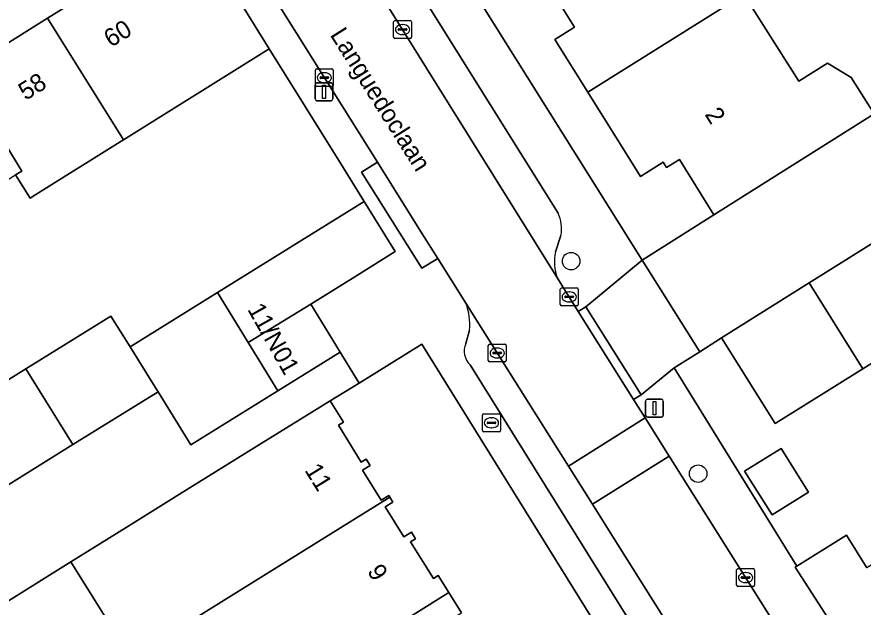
# Model space of a CAD drawing. Extents: x 157767 to 159172, y 387839 to 389425.
# Drawn here: x 158537.73 to 158585.08, y 388070.65 to 388103.69 of the extents above; entities that cross this region are included whole.
import ezdxf

# ---------------------------------------------------------------- set-up
doc = ezdxf.new("R2010")
doc.units = 0
for name, color, linetype in [('IMGEO_Boom', 7, 'Continuous'), ('IMGEO_Brandkraan', 7, 'Continuous'), ('IMGEO_Erf', 7, 'Continuous'), ('IMGEO_Kolk', 7, 'Continuous'), ('IMGEO_Lichtmast', 7, 'Continuous'), ('IMGEO_Muur', 7, 'Continuous'), ('IMGEO_Openbare_ruimte_label', 7, 'Continuous'), ('IMGEO_Pand', 7, 'Continuous'), ('IMGEO_Pand_nummerreeks', 7, 'Continuous'), ('IMGEO_Parkeervlak_open', 7, 'Continuous'), ('IMGEO_Rijbaan_lokaal_open', 7, 'Continuous'), ('IMGEO_Voetpad_open', 7, 'Continuous')]:
    doc.layers.add(name, color=color, linetype=linetype)

msp = doc.modelspace()

# ---------------------------------------------------------------- linework, layer by layer
at = {"layer": 'IMGEO_Boom'}
for centre in [(158568.743, 388090.013), (158575.85, 388078.115)]:
    msp.add_circle(centre, 0.489, dxfattribs=at)
at = {"layer": 'IMGEO_Brandkraan'}
for p, q in [((158563.785, 388080.537), (158563.785, 388081.389)), ((158563.86, 388081.463), (158564.712, 388081.463)), ((158564.273, 388081.243), (158564.298, 388081.243)), ((158564.786, 388081.389), (158564.786, 388080.537)), ((158564.044, 388080.957), (158564.044, 388080.969)), ((158564.482, 388080.92), (158564.084, 388080.92)), ((158564.087, 388081.006), (158564.485, 388081.006)), ((158564.296, 388080.683), (158564.271, 388080.683)), ((158564.528, 388080.969), (158564.528, 388080.957)), ((158564.712, 388080.463), (158563.86, 388080.463))]:
    msp.add_line(p, q, dxfattribs=at)
for points in [[(158563.785, 388080.537), (158563.785, 388081.389)], [(158563.86, 388081.463), (158564.712, 388081.463)], [(158564.786, 388081.389), (158564.786, 388080.537)], [(158564.712, 388080.463), (158563.86, 388080.463)]]:
    msp.add_lwpolyline(points, dxfattribs=at)
for centre, radius, start, end in [((158563.862, 388081.387), 0.0765, 91.552, 178.448), ((158563.862, 388081.387), 0.0765, 91.552, 178.448), ((158564.71, 388081.387), 0.0765, 1.552, 88.448), ((158564.71, 388081.387), 0.0765, 1.552, 88.448), ((158564.084, 388080.966), 0.0403, 85.8775, 175.7526), ((158564.081, 388080.956), 0.0366, 178.938, 274.7102), ((158564.485, 388080.963), 0.043, 264.8664, 352.4533), ((158564.489, 388080.968), 0.0386, 1.7309, 96.639), ((158563.862, 388080.539), 0.0765, 181.552, 268.448), ((158563.862, 388080.539), 0.0765, 181.552, 268.448), ((158564.71, 388080.539), 0.0765, 271.552, 358.448), ((158564.71, 388080.539), 0.0765, 271.552, 358.448)]:
    msp.add_arc(centre, radius, start, end, dxfattribs=at)
for centre, major_axis, ratio, start_param, end_param in [((158564.272, 388080.963), (-0.387, 0.002), 0.722429, 4.712389, 7.853982), ((158564.297, 388080.963), (-0.39, 0.002), 0.717154, 1.570796, 4.712389)]:
    msp.add_ellipse(centre, major_axis=major_axis, ratio=ratio, start_param=start_param, end_param=end_param, dxfattribs=at)
at = {"layer": 'IMGEO_Erf'}
for points in [[(158559.15, 388140.002), (158562.16, 388135.2), (158560.23, 388133.99), (158563.255, 388129.158), (158565.829, 388130.764), (158568.828, 388125.956), (158571.824, 388121.153), (158574.89, 388116.238), (158574.652, 388116.087), (158577.666, 388111.254), (158580.054, 388112.773), (158583.085, 388107.915), (158580.691, 388106.405), (158578.413, 388104.968), (158581.484, 388100.084), (158583.099, 388101.1), (158584.422, 388100.295), (158585.707, 388098.251)], [(158543.307, 388136.995), (158572.727, 388090.067), (158576.734, 388092.607), (158574.802, 388095.703), (158574.08, 388095.253), (158573.894, 388095.549), (158572.625, 388094.751), (158569.685, 388099.464), (158567.84, 388102.421), (158568.941, 388103.113), (158567.783, 388104.969)], [(158541.987, 388115.359), (158534.664, 388110.788), (158510.476, 388095.689), (158512.627, 388092.242), (158517.684, 388095.387), (158522.533, 388098.402), (158527.384, 388101.418), (158532.27, 388104.457), (158532.411, 388104.544), (158534.792, 388100.714), (158539.451, 388103.611), (158544.354, 388106.66)], [(158533.374, 388080.964), (158538.233, 388083.979), (158542.994, 388086.934), (158544.064, 388085.21), (158548.959, 388088.251), (158557.163, 388093.348), (158555.739, 388095.641), (158553.86, 388098.665), (158551.851, 388101.897), (158543.694, 388096.806), (158543.505, 388096.688), (158538.796, 388093.749), (158538.463, 388093.541), (158537.658, 388094.843)], [(158589.913, 388087.032), (158585.067, 388083.993), (158580.171, 388080.923), (158577.165, 388085.719), (158575.941, 388084.94), (158574.516, 388084.034), (158581.379, 388072.944), (158584.145, 388074.678), (158585.3, 388072.835)], [(158581.483, 388051.362), (158560.399, 388085.371), (158556.878, 388083.191), (158555.259, 388082.188), (158555.997, 388080.999), (158555.724, 388080.83), (158557.002, 388078.767), (158557.274, 388078.935), (158557.5, 388078.57), (158557.075, 388078.306), (158558.117, 388076.625), (158558.542, 388076.887), (158558.596, 388076.799), (158558.767, 388076.523), (158558.342, 388076.258), (158559.384, 388074.577), (158559.808, 388074.84), (158560.034, 388074.474), (158559.762, 388074.305), (158561.041, 388072.243), (158561.312, 388072.41), (158561.897, 388071.468), (158562.608, 388070.322)], [(158544.119, 388067.774), (158540.75, 388073.178), (158533.751, 388068.822)]]:
    msp.add_lwpolyline(points, dxfattribs=at)
msp.add_lwpolyline([(158582.025, 388077.082), (158579.988, 388075.805), (158578.452, 388078.255), (158580.489, 388079.532)], close=True, dxfattribs=at)
at = {"layer": 'IMGEO_Kolk'}
for p, q in [((158558.812, 388102.552), (158558.812, 388103.404)), ((158558.887, 388103.478), (158559.739, 388103.478)), ((158559.813, 388103.404), (158559.813, 388102.552)), ((158559.071, 388102.972), (158559.071, 388102.984)), ((158559.509, 388102.935), (158559.111, 388102.935)), ((158559.114, 388103.021), (158559.512, 388103.021)), ((158559.3, 388103.258), (158559.325, 388103.258)), ((158559.555, 388102.984), (158559.555, 388102.972)), ((158559.739, 388102.478), (158558.887, 388102.478)), ((158559.323, 388102.698), (158559.298, 388102.698)), ((158554.433, 388099.859), (158554.433, 388100.711)), ((158554.508, 388100.785), (158555.36, 388100.785)), ((158554.921, 388100.565), (158554.946, 388100.565)), ((158555.434, 388100.711), (158555.434, 388099.859)), ((158554.692, 388100.279), (158554.692, 388100.291)), ((158555.13, 388100.242), (158554.732, 388100.242)), ((158554.735, 388100.328), (158555.133, 388100.328)), ((158555.176, 388100.291), (158555.176, 388100.279)), ((158555.36, 388099.785), (158554.508, 388099.785)), ((158554.944, 388100.005), (158554.919, 388100.005)), ((158568.137, 388087.586), (158568.137, 388088.438)), ((158568.212, 388088.512), (158569.064, 388088.512)), ((158568.625, 388088.292), (158568.65, 388088.292)), ((158569.138, 388088.438), (158569.138, 388087.586)), ((158568.396, 388088.006), (158568.396, 388088.018)), ((158568.834, 388087.969), (158568.436, 388087.969)), ((158568.439, 388088.055), (158568.837, 388088.055)), ((158568.88, 388088.018), (158568.88, 388088.006)), ((158569.064, 388087.512), (158568.212, 388087.512)), ((158568.648, 388087.732), (158568.623, 388087.732)), ((158564.109, 388084.445), (158564.109, 388085.297)), ((158564.184, 388085.371), (158565.036, 388085.371)), ((158564.411, 388084.914), (158564.809, 388084.914)), ((158564.597, 388085.151), (158564.622, 388085.151)), ((158565.11, 388085.297), (158565.11, 388084.445)), ((158564.368, 388084.865), (158564.368, 388084.877)), ((158564.806, 388084.828), (158564.408, 388084.828)), ((158564.62, 388084.591), (158564.595, 388084.591)), ((158564.852, 388084.877), (158564.852, 388084.865)), ((158565.036, 388084.371), (158564.184, 388084.371)), ((158578.006, 388071.872), (158578.006, 388072.724)), ((158578.081, 388072.798), (158578.933, 388072.798)), ((158579.007, 388072.724), (158579.007, 388071.872)), ((158578.265, 388072.292), (158578.265, 388072.304)), ((158578.703, 388072.255), (158578.305, 388072.255)), ((158578.308, 388072.341), (158578.706, 388072.341)), ((158578.494, 388072.578), (158578.519, 388072.578)), ((158578.749, 388072.304), (158578.749, 388072.292)), ((158578.933, 388071.798), (158578.081, 388071.798)), ((158578.517, 388072.018), (158578.492, 388072.018))]:
    msp.add_line(p, q, dxfattribs=at)
for points in [[(158558.812, 388102.552), (158558.812, 388103.404)], [(158558.887, 388103.478), (158559.739, 388103.478)], [(158559.813, 388103.404), (158559.813, 388102.552)], [(158559.739, 388102.478), (158558.887, 388102.478)], [(158554.433, 388099.859), (158554.433, 388100.711)], [(158554.508, 388100.785), (158555.36, 388100.785)], [(158555.434, 388100.711), (158555.434, 388099.859)], [(158555.36, 388099.785), (158554.508, 388099.785)], [(158568.137, 388087.586), (158568.137, 388088.438)], [(158568.212, 388088.512), (158569.064, 388088.512)], [(158569.138, 388088.438), (158569.138, 388087.586)], [(158569.064, 388087.512), (158568.212, 388087.512)], [(158564.109, 388084.445), (158564.109, 388085.297)], [(158564.184, 388085.371), (158565.036, 388085.371)], [(158565.11, 388085.297), (158565.11, 388084.445)], [(158565.036, 388084.371), (158564.184, 388084.371)], [(158578.006, 388071.872), (158578.006, 388072.724)], [(158578.081, 388072.798), (158578.933, 388072.798)], [(158579.007, 388072.724), (158579.007, 388071.872)], [(158578.933, 388071.798), (158578.081, 388071.798)]]:
    msp.add_lwpolyline(points, dxfattribs=at)
for centre, radius, start, end in [((158558.889, 388103.402), 0.0765, 91.552, 178.448), ((158558.889, 388103.402), 0.0765, 91.552, 178.448), ((158559.737, 388103.402), 0.0765, 1.552, 88.448), ((158559.737, 388103.402), 0.0765, 1.552, 88.448), ((158559.111, 388102.981), 0.0403, 85.8775, 175.7526), ((158559.108, 388102.971), 0.0366, 178.938, 274.7102), ((158559.512, 388102.978), 0.043, 264.8664, 352.4533), ((158559.516, 388102.983), 0.0386, 1.7309, 96.639), ((158558.889, 388102.554), 0.0765, 181.552, 268.448), ((158558.889, 388102.554), 0.0765, 181.552, 268.448), ((158559.737, 388102.554), 0.0765, 271.552, 358.448), ((158559.737, 388102.554), 0.0765, 271.552, 358.448), ((158554.51, 388100.709), 0.0765, 91.552, 178.448), ((158554.51, 388100.709), 0.0765, 91.552, 178.448), ((158555.358, 388100.709), 0.0765, 1.552, 88.448), ((158555.358, 388100.709), 0.0765, 1.552, 88.448), ((158554.732, 388100.288), 0.0403, 85.8775, 175.7526), ((158554.729, 388100.278), 0.0366, 178.938, 274.7102), ((158555.133, 388100.285), 0.043, 264.8664, 352.4533), ((158555.137, 388100.29), 0.0386, 1.7309, 96.639), ((158554.51, 388099.861), 0.0765, 181.552, 268.448), ((158554.51, 388099.861), 0.0765, 181.552, 268.448), ((158555.358, 388099.861), 0.0765, 271.552, 358.448), ((158555.358, 388099.861), 0.0765, 271.552, 358.448), ((158568.214, 388088.436), 0.0765, 91.552, 178.448), ((158568.214, 388088.436), 0.0765, 91.552, 178.448), ((158569.062, 388088.436), 0.0765, 1.552, 88.448), ((158569.062, 388088.436), 0.0765, 1.552, 88.448), ((158568.436, 388088.015), 0.0403, 85.8775, 175.7526), ((158568.433, 388088.005), 0.0366, 178.938, 274.7102), ((158568.837, 388088.012), 0.043, 264.8664, 352.4533), ((158568.841, 388088.017), 0.0386, 1.7309, 96.639), ((158568.214, 388087.588), 0.0765, 181.552, 268.448), ((158568.214, 388087.588), 0.0765, 181.552, 268.448), ((158569.062, 388087.588), 0.0765, 271.552, 358.448), ((158569.062, 388087.588), 0.0765, 271.552, 358.448), ((158564.186, 388085.295), 0.0765, 91.552, 178.448), ((158564.186, 388085.295), 0.0765, 91.552, 178.448), ((158564.408, 388084.874), 0.0403, 85.8775, 175.7526), ((158564.813, 388084.876), 0.0386, 1.7309, 96.639), ((158565.034, 388085.295), 0.0765, 1.552, 88.448), ((158565.034, 388085.295), 0.0765, 1.552, 88.448), ((158564.186, 388084.447), 0.0765, 181.552, 268.448), ((158564.186, 388084.447), 0.0765, 181.552, 268.448), ((158564.405, 388084.864), 0.0366, 178.938, 274.7102), ((158564.809, 388084.871), 0.043, 264.8664, 352.4533), ((158565.034, 388084.447), 0.0765, 271.552, 358.448), ((158565.034, 388084.447), 0.0765, 271.552, 358.448), ((158578.083, 388072.722), 0.0765, 91.552, 178.448), ((158578.083, 388072.722), 0.0765, 91.552, 178.448), ((158578.931, 388072.722), 0.0765, 1.552, 88.448), ((158578.931, 388072.722), 0.0765, 1.552, 88.448), ((158578.305, 388072.301), 0.0403, 85.8775, 175.7526), ((158578.302, 388072.291), 0.0366, 178.938, 274.7102), ((158578.706, 388072.298), 0.043, 264.8664, 352.4533), ((158578.71, 388072.303), 0.0386, 1.7309, 96.639), ((158578.083, 388071.874), 0.0765, 181.552, 268.448), ((158578.083, 388071.874), 0.0765, 181.552, 268.448), ((158578.931, 388071.874), 0.0765, 271.552, 358.448), ((158578.931, 388071.874), 0.0765, 271.552, 358.448)]:
    msp.add_arc(centre, radius, start, end, dxfattribs=at)
for centre, major_axis, ratio, start_param, end_param in [((158559.299, 388102.978), (-0.387, 0.002), 0.722429, 4.712389, 7.853982), ((158559.324, 388102.978), (-0.39, 0.002), 0.717154, 1.570796, 4.712389), ((158554.92, 388100.285), (-0.387, 0.002), 0.722429, 4.712389, 7.853982), ((158554.945, 388100.285), (-0.39, 0.002), 0.717154, 1.570796, 4.712389), ((158568.624, 388088.012), (-0.387, 0.002), 0.722429, 4.712389, 7.853982), ((158568.649, 388088.012), (-0.39, 0.002), 0.717154, 1.570796, 4.712389), ((158564.596, 388084.871), (-0.387, 0.002), 0.722429, 4.712389, 7.853982), ((158564.621, 388084.871), (-0.39, 0.002), 0.717154, 1.570796, 4.712389), ((158578.493, 388072.298), (-0.387, 0.002), 0.722429, 4.712389, 7.853982), ((158578.518, 388072.298), (-0.39, 0.002), 0.717154, 1.570796, 4.712389)]:
    msp.add_ellipse(centre, major_axis=major_axis, ratio=ratio, start_param=start_param, end_param=end_param, dxfattribs=at)
at = {"layer": 'IMGEO_Lichtmast'}
for p, q in [((158554.42, 388099.093), (158554.42, 388099.893)), ((158554.42, 388099.893), (158554.42, 388099.093)), ((158554.52, 388099.993), (158555.31, 388099.993)), ((158555.31, 388099.993), (158554.52, 388099.993)), ((158555.41, 388099.893), (158555.41, 388099.093)), ((158555.41, 388099.093), (158555.41, 388099.893)), ((158555.31, 388098.993), (158554.52, 388098.993)), ((158554.52, 388098.993), (158555.31, 388098.993)), ((158572.912, 388081.38), (158572.912, 388082.18)), ((158572.912, 388082.18), (158572.912, 388081.38)), ((158573.012, 388082.28), (158573.802, 388082.28)), ((158573.802, 388082.28), (158573.012, 388082.28)), ((158573.902, 388082.18), (158573.902, 388081.38)), ((158573.902, 388081.38), (158573.902, 388082.18)), ((158573.802, 388081.28), (158573.012, 388081.28)), ((158573.012, 388081.28), (158573.802, 388081.28))]:
    msp.add_line(p, q, dxfattribs=at)
for points in [[(158554.84, 388099.868), (158554.99, 388099.868), (158554.99, 388099.118), (158554.84, 388099.118), (158554.84, 388099.868)], [(158573.332, 388082.155), (158573.482, 388082.155), (158573.482, 388081.405), (158573.332, 388081.405), (158573.332, 388082.155)]]:
    msp.add_lwpolyline(points, dxfattribs=at)
for centre, start, end in [((158554.52, 388099.893), 90, 180), ((158554.52, 388099.893), 90, 180), ((158555.31, 388099.893), 0, 90), ((158555.31, 388099.893), 360, 90), ((158554.52, 388099.093), 180, 270), ((158554.52, 388099.093), 180, 270), ((158555.31, 388099.093), 270, 0), ((158555.31, 388099.093), 270, 0), ((158573.012, 388082.18), 90, 180), ((158573.012, 388082.18), 90, 180), ((158573.802, 388082.18), 0, 90), ((158573.802, 388082.18), 360, 90), ((158573.012, 388081.38), 180, 270), ((158573.012, 388081.38), 180, 270), ((158573.802, 388081.38), 270, 0), ((158573.802, 388081.38), 270, 0)]:
    msp.add_arc(centre, 0.1, start, end, dxfattribs=at)
at = {"layer": 'IMGEO_Muur'}
for points in [[(158551.851, 388101.897), (158553.86, 388098.665), (158555.739, 388095.641)], [(158555.739, 388095.641), (158557.163, 388093.348)], [(158581.379, 388072.944), (158574.516, 388084.034)]]:
    msp.add_lwpolyline(points, dxfattribs=at)
at = {"layer": 'IMGEO_Pand'}
for points in [[(158583.085, 388107.915), (158580.054, 388112.773), (158577.666, 388111.254), (158567.951, 388105.076), (158567.783, 388104.969), (158568.941, 388103.113), (158567.84, 388102.421), (158569.685, 388099.464), (158578.413, 388104.968), (158580.691, 388106.405)], [(158551.851, 388101.897), (158550.45, 388104.152), (158546.665, 388105.92), (158545.331, 388105.09), (158544.354, 388106.66), (158539.451, 388103.611), (158543.694, 388096.806)], [(158584.422, 388100.295), (158583.099, 388101.1), (158581.484, 388100.084), (158578.413, 388104.968), (158569.685, 388099.464), (158572.625, 388094.751), (158573.894, 388095.549), (158574.08, 388095.253), (158574.802, 388095.703), (158576.734, 388092.607), (158585.707, 388098.251)], [(158534.617, 388100.605), (158534.792, 388100.714), (158532.411, 388104.544), (158532.27, 388104.457), (158527.384, 388101.418), (158533.21, 388092.077), (158537.658, 388094.843), (158538, 388095.056)], [(158539.451, 388103.611), (158534.792, 388100.714), (158534.617, 388100.605), (158538, 388095.056), (158537.658, 388094.843), (158538.463, 388093.541), (158538.796, 388093.749), (158543.505, 388096.688), (158543.694, 388096.806)], [(158550.668, 388085.461), (158554.172, 388087.608), (158556.64, 388089.139), (158558.904, 388090.545), (158557.163, 388093.348), (158548.959, 388088.251)], [(158586.899, 388091.823), (158582.069, 388088.794), (158585.067, 388083.993), (158589.913, 388087.032)], [(158585.067, 388083.993), (158582.069, 388088.794), (158577.165, 388085.719), (158580.171, 388080.923)], [(158550.668, 388085.461), (158548.959, 388088.251), (158544.064, 388085.21), (158545.373, 388083.1), (158545.626, 388082.705), (158547.466, 388079.739), (158552.326, 388082.755)], [(158550.668, 388085.461), (158552.326, 388082.755), (158555.818, 388084.922), (158554.172, 388087.608)], [(158545.373, 388083.1), (158544.064, 388085.21), (158542.994, 388086.934), (158538.233, 388083.979), (158540.862, 388079.749), (158545.626, 388082.705)], [(158540.862, 388079.749), (158538.233, 388083.979), (158533.374, 388080.964), (158536.057, 388076.767)], [(158558.596, 388076.799), (158558.542, 388076.887), (158558.117, 388076.625), (158557.075, 388078.306), (158557.5, 388078.57), (158557.274, 388078.935), (158557.002, 388078.767), (158555.724, 388080.83), (158555.997, 388080.999), (158555.259, 388082.188), (158551.008, 388079.556), (158546.824, 388076.965), (158543.839, 388075.104), (158540.75, 388073.178), (158544.119, 388067.774), (158547.208, 388069.7), (158550.177, 388071.551)], [(158578.452, 388078.255), (158579.988, 388075.805), (158582.025, 388077.082), (158580.489, 388079.532)], [(158551.465, 388064.936), (158561.897, 388071.468), (158561.312, 388072.41), (158561.041, 388072.243), (158559.762, 388074.305), (158560.034, 388074.474), (158559.808, 388074.84), (158559.384, 388074.577), (158558.342, 388076.258), (158558.767, 388076.523), (158558.596, 388076.799), (158550.177, 388071.551), (158547.208, 388069.7), (158550.538, 388064.358)], [(158590.193, 388075.903), (158585.3, 388072.835), (158584.145, 388074.678), (158581.379, 388072.944), (158581.281, 388072.883), (158584.968, 388067.145), (158587.528, 388068.75), (158589.446, 388065.691), (158594.284, 388068.725), (158594.557, 388068.896)], [(158565.22, 388066.102), (158565.153, 388066.21), (158564.729, 388065.948), (158563.687, 388067.629), (158564.111, 388067.894), (158563.885, 388068.258), (158563.614, 388068.09), (158562.335, 388070.153), (158562.608, 388070.322), (158561.897, 388071.468), (158551.465, 388064.936), (158554.783, 388059.578), (158556.813, 388060.835)]]:
    msp.add_lwpolyline(points, close=True, dxfattribs=at)
at = {"layer": 'IMGEO_Parkeervlak_open'}
for points in [[(158542.515, 388132.757), (158541.269, 388133.08), (158540.153, 388133.606), (158540.834, 388132.511), (158554.594, 388110.551), (158567.978, 388089.064)], [(158568.014, 388092.699), (158543.28, 388132.254)], [(158567.868, 388090.53), (158568.176, 388091.448)], [(158582.268, 388056.746), (158581.434, 388058.111), (158570.744, 388075.126), (158569.941, 388076.402), (158568.599, 388078.534), (158562.853, 388087.665)], [(158563.056, 388086.148), (158562.845, 388085.398)], [(158563.093, 388084.206), (158579.251, 388058.252)]]:
    msp.add_lwpolyline(points, dxfattribs=at)
for centre, radius, start, end in [((158566.156, 388091.822), 2.054, 349.4961, 25.261), ((158570.28, 388089.974), 2.475, 167.0132, 201.569), ((158559.783, 388086.482), 3.29, 354.1721, 21.0716), ((158563.843, 388084.984), 1.08, 157.4493, 226.0566)]:
    msp.add_arc(centre, radius, start, end, dxfattribs=at)
at = {"layer": 'IMGEO_Rijbaan_lokaal_open'}
for points in [[(158545.224, 388115.783), (158557.903, 388095.549), (158560.409, 388091.549), (158561.277, 388090.169), (158562.853, 388087.665), (158568.599, 388078.534), (158572.893, 388081.234), (158572.243, 388082.269), (158569.145, 388087.201), (158568.373, 388088.43), (158567.978, 388089.064), (158554.594, 388110.551), (158540.834, 388132.511)], [(158585.707, 388098.251), (158576.734, 388092.607), (158572.727, 388090.067), (158575.941, 388084.94), (158577.165, 388085.719), (158582.069, 388088.794), (158586.899, 388091.823)], [(158580.717, 388068.777), (158574.233, 388079.1), (158569.941, 388076.402), (158570.744, 388075.126), (158581.434, 388058.111), (158582.268, 388056.746), (158584.053, 388053.823)]]:
    msp.add_lwpolyline(points, dxfattribs=at)
for points in [[(158546.824, 388076.965), (158551.008, 388079.556), (158555.259, 388082.188), (158556.878, 388083.191), (158555.818, 388084.922), (158552.326, 388082.755), (158547.466, 388079.739), (158545.626, 388082.705), (158540.862, 388079.749), (158536.057, 388076.767), (158531.198, 388073.751), (158526.126, 388070.604), (158529.064, 388065.9), (158533.751, 388068.822), (158540.75, 388073.178), (158543.839, 388075.104)], [(158569.941, 388076.402), (158574.233, 388079.1), (158572.893, 388081.234), (158568.599, 388078.534)]]:
    msp.add_lwpolyline(points, close=True, dxfattribs=at)
at = {"layer": 'IMGEO_Voetpad_open'}
for points in [[(158567.978, 388089.064), (158568.373, 388088.43), (158569.145, 388087.201), (158569.57, 388087.464), (158572.727, 388090.067), (158543.307, 388136.995)], [(158543.28, 388132.254), (158568.014, 388092.699)], [(158562.853, 388087.665), (158561.277, 388090.169), (158560.394, 388089.621), (158557.019, 388095), (158557.903, 388095.549), (158545.224, 388115.783)], [(158543.728, 388114.955), (158550.45, 388104.152), (158551.851, 388101.897), (158553.86, 388098.665), (158555.739, 388095.641), (158557.163, 388093.348), (158558.904, 388090.545), (158556.64, 388089.139), (158554.172, 388087.608), (158555.818, 388084.922), (158556.878, 388083.191), (158560.399, 388085.371), (158581.483, 388051.362)], [(158568.176, 388091.448), (158567.868, 388090.53)], [(158562.845, 388085.398), (158563.056, 388086.148)], [(158579.251, 388058.252), (158563.093, 388084.206)], [(158584.968, 388067.145), (158581.281, 388072.883), (158581.379, 388072.944), (158574.516, 388084.034), (158572.668, 388082.532), (158572.243, 388082.269), (158572.893, 388081.234), (158574.233, 388079.1), (158580.717, 388068.777), (158588.162, 388056.973)]]:
    msp.add_lwpolyline(points, dxfattribs=at)
for points in [[(158557.903, 388095.549), (158557.019, 388095), (158560.394, 388089.621), (158561.277, 388090.169), (158560.409, 388091.549)], [(158572.727, 388090.067), (158569.57, 388087.464), (158572.668, 388082.532), (158574.516, 388084.034), (158575.941, 388084.94)], [(158572.243, 388082.269), (158572.668, 388082.532), (158569.57, 388087.464), (158569.145, 388087.201)]]:
    msp.add_lwpolyline(points, close=True, dxfattribs=at)
for centre, radius, start, end in [((158566.156, 388091.822), 2.054, 349.4961, 25.261), ((158570.28, 388089.974), 2.475, 167.0132, 201.569), ((158559.783, 388086.482), 3.29, 354.1721, 21.0716), ((158563.843, 388084.984), 1.08, 157.4493, 226.0566)]:
    msp.add_arc(centre, radius, start, end, dxfattribs=at)

# ---------------------------------------------------------------- texts
at = {"layer": 'IMGEO_Openbare_ruimte_label'}
msp.add_text('Languedoclaan', height=1, rotation=302.2119, dxfattribs=at).set_placement((158555.225, 388102.684))
at = {"layer": 'IMGEO_Pand_nummerreeks'}
for s, rotation, p in [('60', 31.8736, (158542.996, 388101.953)), ('58', 31.8736, (158538.215, 388098.98)), ('2', 301.9651, (158576.195, 388098.231)), ('11/N01', 299.3578, (158550.607, 388087.318)), ('11', 301.7646, (158553.804, 388078.308)), ('9', 301.7668, (158557.306, 388072.652))]:
    msp.add_text(s, height=1, rotation=rotation, dxfattribs=at).set_placement(p)

doc.saveas('drawing.dxf')
